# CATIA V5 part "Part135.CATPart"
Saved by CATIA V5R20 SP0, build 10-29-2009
Part number: FA 084700-1
Revision: ANY
Definition: UNKNOWN
Nomenclature: FA 084700-1
Source: Unknown
Bounding box of the stored display mesh (mm): x -2.853 to 2.853, y 0.2 to 2.5, z -3 to 3
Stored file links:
  C:\Users\Utente\Desktop\IO LAVORO\3D X SITO CF\CUMSA\3D files FA\FA 084712-20\Part135.CATPart

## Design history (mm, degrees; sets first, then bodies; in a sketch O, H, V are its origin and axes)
Body1 "Cortar-Extruir1" (main body)
  Solid1: solid without history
